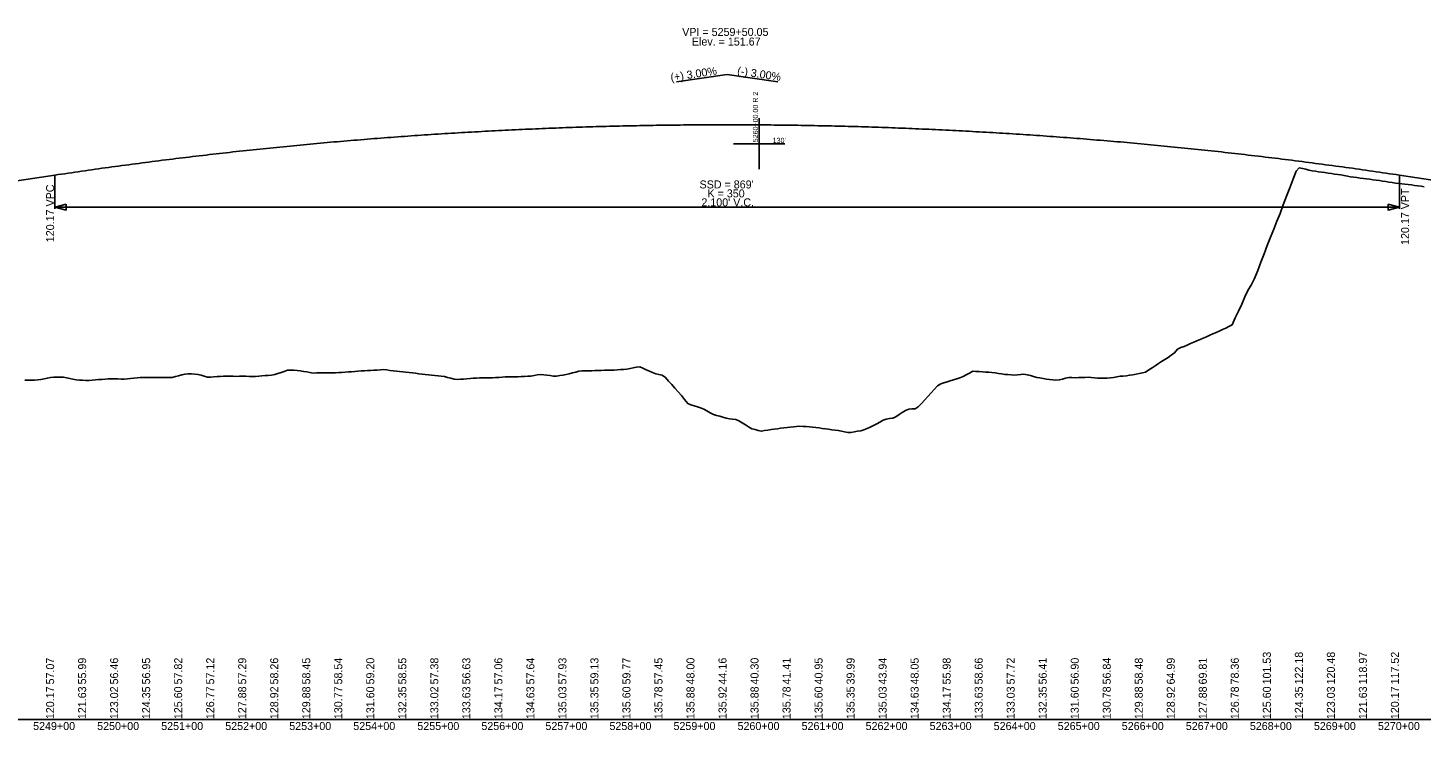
# Model space of a CAD drawing. Extents: x 2147288 to 2220488, y 740833 to 759333.
# Drawn here: x 2157239 to 2159415, y 742067 to 743164 of the extents above; entities that cross this region are included whole.
import ezdxf

# ---------------------------------------------------------------- set-up
doc = ezdxf.new("R2010")
doc.units = 0
for name, color, linetype in [('RD_DDB_GradeTX', 7, 'Continuous'), ('RD_DDB_Profile_EX', 7, 'Continuous'), ('RD_DDB_Profile_Lbl', 7, 'Continuous'), ('RD_DDB_Profile_PR', 7, 'Continuous'), ('RD_DDB_StaTX', 7, 'Continuous'), ('RD_DDB_StripGrade', 7, 'Continuous'), ('RD_DDB_VCLbl', 7, 'Continuous'), ('RD_GPK_Profile_Cell', 7, 'Continuous')]:
    doc.layers.add(name, color=color, linetype=linetype)

msp = doc.modelspace()

# ---------------------------------------------------------------- linework, layer by layer
at = {"layer": 'RD_DDB_GradeTX'}
for p in [(2158252, 743079.9), (2158410.2, 743079.9)]:
    msp.add_line(p, (2158331.1, 743091.8), dxfattribs=at)
at = {"layer": 'RD_DDB_Profile_EX'}
for points in [[(2159034.6, 742662.3), (2159039.6, 742664.7), (2159044.6, 742666.7), (2159049.6, 742668.8), (2159054.6, 742671), (2159059.6, 742673.2), (2159064.6, 742675.3), (2159069.6, 742677.5), (2159074.6, 742679.7), (2159079.6, 742681.8), (2159084.6, 742684), (2159089.6, 742686.2), (2159094.6, 742688.4), (2159099.6, 742690.5), (2159104.6, 742692.9), (2159109.6, 742695.3), (2159114.6, 742697.7), (2159119.6, 742700.4), (2159124.6, 742711.5), (2159129.6, 742721.9), (2159134.6, 742732.9), (2159139.6, 742744.3), (2159144.6, 742754.9), (2159149.6, 742762.3), (2159154.6, 742772.9), (2159159.6, 742785.4), (2159164.6, 742798.2), (2159169.6, 742811.2), (2159174.6, 742824.3), (2159179.6, 742837.3), (2159184.6, 742850), (2159189.6, 742862.4), (2159194.6, 742874.5), (2159199.6, 742887.8), (2159204.6, 742901.4), (2159209.6, 742914.5), (2159214.6, 742927.2), (2159219.6, 742940.4), (2159224.6, 742945.5), (2159229.6, 742944.7), (2159234.6, 742943.5), (2159239.6, 742942.3), (2159244.6, 742941.1), (2159249.6, 742940.4), (2159254.6, 742939.7), (2159259.6, 742939), (2159264.6, 742938.3), (2159269.6, 742937.5), (2159274.6, 742936.7), (2159279.6, 742936), (2159284.6, 742935.3), (2159289.6, 742934.6), (2159294.6, 742933.6), (2159299.6, 742932.7), (2159304.6, 742931.9), (2159309.6, 742931.2), (2159314.6, 742930.5), (2159319.6, 742929.8), (2159324.6, 742929.1), (2159329.6, 742928.5), (2159334.6, 742927.8), (2159339.6, 742927), (2159344.6, 742926.3), (2159349.6, 742925.7), (2159354.6, 742925), (2159359.6, 742924.2), (2159364.6, 742923.4), (2159369.6, 742922.7), (2159374.6, 742921.9), (2159379.6, 742921.2), (2159384.6, 742920.6), (2159389.6, 742920.2), (2159394.6, 742919.5), (2159399.6, 742918.9), (2159404.6, 742918.2), (2159409.6, 742917.6), (2159414.6, 742916.9), (2159419.6, 742916.2)], [(2158534.6, 742534), (2158539.6, 742534.8), (2158544.6, 742536.4), (2158549.6, 742538.4), (2158554.6, 742540.4), (2158559.6, 742542.9), (2158564.6, 742545.6), (2158569.6, 742548.4), (2158574.6, 742551.2), (2158579.6, 742552.8), (2158584.6, 742553.8), (2158589.6, 742554.7), (2158594.6, 742556.8), (2158599.6, 742560.1), (2158604.6, 742563.4), (2158609.6, 742566.7), (2158614.6, 742568.5), (2158619.6, 742568.9), (2158624.6, 742569.3), (2158629.6, 742572), (2158634.6, 742577.5), (2158639.6, 742583), (2158644.6, 742588.5), (2158649.6, 742594), (2158654.6, 742599.5), (2158659.6, 742605), (2158664.6, 742608.3), (2158669.6, 742609.8), (2158674.6, 742611.3), (2158679.6, 742612.8), (2158684.6, 742614.4), (2158689.6, 742616.1), (2158694.6, 742617.7), (2158699.6, 742619.4), (2158704.6, 742622.2), (2158709.6, 742625.1), (2158714.6, 742627.9), (2158719.6, 742627.5), (2158724.6, 742627.2), (2158729.6, 742626.8), (2158734.6, 742626.5), (2158739.6, 742626.2), (2158744.6, 742625.9), (2158749.6, 742625.3), (2158754.6, 742624.5), (2158759.6, 742623.7), (2158764.6, 742622.9), (2158769.6, 742622.6), (2158774.6, 742622.3), (2158779.6, 742621.9), (2158784.6, 742622.1), (2158789.6, 742622.6), (2158794.6, 742623.1), (2158799.6, 742622.4), (2158804.6, 742621), (2158809.6, 742619.6), (2158814.6, 742618.3), (2158819.6, 742617.4), (2158824.6, 742616.5), (2158829.6, 742615.7), (2158834.6, 742615), (2158839.6, 742614.4), (2158844.6, 742613.7), (2158849.6, 742614.3), (2158854.6, 742615.7), (2158859.6, 742617), (2158864.6, 742618), (2158869.6, 742617.9), (2158874.6, 742617.8), (2158879.6, 742617.9), (2158884.6, 742618), (2158889.6, 742618.2), (2158894.6, 742618.4), (2158899.6, 742618.1), (2158904.6, 742617.6), (2158909.6, 742617.1), (2158914.6, 742617), (2158919.6, 742617), (2158924.6, 742617), (2158929.6, 742617.4), (2158934.6, 742618.2), (2158939.6, 742619.1), (2158944.6, 742620), (2158949.6, 742620.4), (2158954.6, 742620.8), (2158959.6, 742621.5), (2158964.6, 742622.4), (2158969.6, 742623.3), (2158974.6, 742624.4), (2158979.6, 742625.5), (2158984.6, 742626.6), (2158989.6, 742629.9), (2158994.6, 742633.1), (2158999.6, 742636.4), (2159004.6, 742639.7), (2159009.6, 742642.9), (2159014.6, 742646.2), (2159019.6, 742649.4), (2159024.6, 742652.8), (2159029.6, 742656.7), (2159034.6, 742662.3)], [(2157534.6, 742619.4), (2157539.6, 742619.8), (2157544.6, 742619.9), (2157549.6, 742619.9), (2157554.6, 742620), (2157559.6, 742619.9), (2157564.6, 742619.8), (2157569.6, 742620), (2157574.6, 742620.1), (2157579.6, 742619.9), (2157584.6, 742619.7), (2157589.6, 742619.5), (2157594.6, 742619.7), (2157599.6, 742620.1), (2157604.6, 742620.6), (2157609.6, 742621), (2157614.6, 742621.3), (2157619.6, 742621.7), (2157624.6, 742622.5), (2157629.6, 742624.2), (2157634.6, 742626), (2157639.6, 742627.7), (2157644.6, 742629.5), (2157649.6, 742629.5), (2157654.6, 742629.4), (2157659.6, 742629.2), (2157664.6, 742628.5), (2157669.6, 742627.7), (2157674.6, 742626.8), (2157679.6, 742625.9), (2157684.6, 742625.1), (2157689.6, 742625.3), (2157694.6, 742625.4), (2157699.6, 742625.6), (2157704.6, 742625.6), (2157709.6, 742625.6), (2157714.6, 742625.6), (2157719.6, 742625.6), (2157724.6, 742625.7), (2157729.6, 742626), (2157734.6, 742626.3), (2157739.6, 742626.7), (2157744.6, 742627.1), (2157749.6, 742627.5), (2157754.6, 742628), (2157759.6, 742628.4), (2157764.6, 742628.7), (2157769.6, 742628.9), (2157774.6, 742629.1), (2157779.6, 742629.3), (2157784.6, 742629.7), (2157789.6, 742630.1), (2157794.6, 742630.4), (2157799.6, 742629.8), (2157804.6, 742629.2), (2157809.6, 742628.7), (2157814.6, 742628.1), (2157819.6, 742627.5), (2157824.6, 742626.9), (2157829.6, 742626.3), (2157834.6, 742625.8), (2157839.6, 742625.2), (2157844.6, 742624.6), (2157849.6, 742624), (2157854.6, 742623.4), (2157859.6, 742622.8), (2157864.6, 742622.3), (2157869.6, 742621.7), (2157874.6, 742621.1), (2157879.6, 742620.5), (2157884.6, 742619.9), (2157889.6, 742619.4), (2157894.6, 742618.3), (2157899.6, 742616.9), (2157904.6, 742615.5), (2157909.6, 742614.9), (2157914.6, 742615.3), (2157919.6, 742615.7), (2157924.6, 742616.1), (2157929.6, 742616.5), (2157934.6, 742616.8), (2157939.6, 742617.2), (2157944.6, 742617.6), (2157949.6, 742617.6), (2157954.6, 742617.6), (2157959.6, 742617.5), (2157964.6, 742617.7), (2157969.6, 742618), (2157974.6, 742618.3), (2157979.6, 742618.6), (2157984.6, 742618.9), (2157989.6, 742618.9), (2157994.6, 742619), (2157999.6, 742619), (2158004.6, 742619.3), (2158009.6, 742619.5), (2158014.6, 742619.8), (2158019.6, 742620), (2158024.6, 742620.4), (2158029.6, 742621.3), (2158034.6, 742622.2)], [(2158034.6, 742622.2), (2158039.6, 742622.8), (2158044.6, 742622.2), (2158049.6, 742621.6), (2158054.6, 742621), (2158059.6, 742620.4), (2158064.6, 742620.4), (2158069.6, 742621), (2158074.6, 742621.7), (2158079.6, 742622.7), (2158084.6, 742624), (2158089.6, 742625.3), (2158094.6, 742626.5), (2158099.6, 742627.8), (2158104.6, 742628.3), (2158109.6, 742628.4), (2158114.6, 742628.5), (2158119.6, 742628.6), (2158124.6, 742628.8), (2158129.6, 742629), (2158134.6, 742629.2), (2158139.6, 742629.4), (2158144.6, 742629.4), (2158149.6, 742629.4), (2158154.6, 742629.4), (2158159.6, 742629.9), (2158164.6, 742630.4), (2158169.6, 742630.8), (2158174.6, 742631.3), (2158179.6, 742631.9), (2158184.6, 742633.2), (2158189.6, 742634.4), (2158194.6, 742634.9), (2158199.6, 742632.6), (2158204.6, 742630.3), (2158209.6, 742628), (2158214.6, 742625.7), (2158219.6, 742624), (2158224.6, 742622.9), (2158229.6, 742621.8), (2158234.6, 742618.2), (2158239.6, 742612.6), (2158244.6, 742607), (2158249.6, 742601.4), (2158254.6, 742595.8), (2158259.6, 742589.8), (2158264.6, 742583.7), (2158269.6, 742577.5), (2158274.6, 742575.5), (2158279.6, 742573.9), (2158284.6, 742572.3), (2158289.6, 742570.7), (2158294.6, 742568.8), (2158299.6, 742565.9), (2158304.6, 742563), (2158309.6, 742560.4), (2158314.6, 742558.9), (2158319.6, 742557.4), (2158324.6, 742556), (2158329.6, 742554.5), (2158334.6, 742553.6), (2158339.6, 742553.2), (2158344.6, 742552.7), (2158349.6, 742550.6), (2158354.6, 742547.4), (2158359.6, 742544.1), (2158364.6, 742540.9), (2158369.6, 742537.9), (2158374.6, 742536.6), (2158379.6, 742535.3), (2158384.6, 742534.2), (2158389.6, 742535), (2158394.6, 742535.8), (2158399.6, 742536.6), (2158404.6, 742537.5), (2158409.6, 742538.1), (2158414.6, 742538.7), (2158419.6, 742539.2), (2158424.6, 742539.8), (2158429.6, 742540.3), (2158434.6, 742540.9), (2158439.6, 742541.4), (2158444.6, 742542), (2158449.6, 742541.7), (2158454.6, 742541.4), (2158459.6, 742541), (2158464.6, 742540.7), (2158469.6, 742540.1), (2158474.6, 742539.3), (2158479.6, 742538.4), (2158484.6, 742537.7), (2158489.6, 742537.1), (2158494.6, 742536.5), (2158499.6, 742535.9), (2158504.6, 742535.4), (2158509.6, 742534.3), (2158514.6, 742533.1), (2158519.6, 742531.9), (2158524.6, 742532.3), (2158529.6, 742533.1), (2158534.6, 742534)], [(2157234.6, 742614), (2157239.6, 742613.9), (2157244.6, 742613.9), (2157249.6, 742613.9), (2157254.6, 742614.2), (2157259.6, 742615.1), (2157264.6, 742616.1), (2157269.6, 742617.1), (2157274.6, 742618), (2157279.6, 742618.8), (2157284.6, 742618.7), (2157289.6, 742618.6), (2157294.6, 742618.4), (2157299.6, 742617.5), (2157304.6, 742616.5), (2157309.6, 742615.5), (2157314.6, 742614.5), (2157319.6, 742614), (2157324.6, 742613.7), (2157329.6, 742613.3), (2157334.6, 742613.4), (2157339.6, 742613.9), (2157344.6, 742614.3), (2157349.6, 742614.8), (2157354.6, 742615.2), (2157359.6, 742615.5), (2157364.6, 742615.8), (2157369.6, 742616.1), (2157374.6, 742615.9), (2157379.6, 742615.8), (2157384.6, 742615.6), (2157389.6, 742615.4), (2157394.6, 742615.9), (2157399.6, 742616.5), (2157404.6, 742617), (2157409.6, 742617.6), (2157414.6, 742617.9), (2157419.6, 742618), (2157424.6, 742618.1), (2157429.6, 742618.2), (2157434.6, 742618.1), (2157439.6, 742618.1), (2157444.6, 742618), (2157449.6, 742618), (2157454.6, 742618.1), (2157459.6, 742618.1), (2157464.6, 742618.2), (2157469.6, 742619.5), (2157474.6, 742620.8), (2157479.6, 742622.2), (2157484.6, 742623.5), (2157489.6, 742623.6), (2157494.6, 742623.6), (2157499.6, 742623.5), (2157504.6, 742622.8), (2157509.6, 742621.5), (2157514.6, 742620.1), (2157519.6, 742618.8), (2157524.6, 742618.4), (2157529.6, 742618.9), (2157534.6, 742619.4)]]:
    msp.add_lwpolyline(points, dxfattribs=at)
at = {"layer": 'RD_DDB_Profile_PR'}
for p, q in [((2156931.1, 742881.8), (2157281.1, 742934.3)), ((2159381.1, 742934.3), (2159706.2, 742885.5))]:
    msp.add_line(p, q, dxfattribs=at)
msp.add_spline([(2157281.1, 742934.3), (2157323.1, 742940.4), (2157365.1, 742946.4), (2157407.1, 742952), (2157449.1, 742957.5), (2157491.1, 742962.6), (2157533.1, 742967.5), (2157575.1, 742972.2), (2157617.1, 742976.6), (2157659.1, 742980.8), (2157701.1, 742984.7), (2157743.1, 742988.3), (2157785.1, 742991.7), (2157827.1, 742994.9), (2157869.1, 742997.8), (2157911.1, 743000.4), (2157953.1, 743002.8), (2157995.1, 743005), (2158037.1, 743006.8), (2158079.1, 743008.5), (2158121.1, 743009.9), (2158163.1, 743011), (2158205.1, 743011.9), (2158247.1, 743012.5), (2158289.1, 743012.9), (2158331.1, 743013), (2158373.1, 743012.9), (2158415.1, 743012.5), (2158457.1, 743011.9), (2158499.1, 743011), (2158541.1, 743009.9), (2158583.1, 743008.5), (2158625.1, 743006.8), (2158667.1, 743005), (2158709.1, 743002.8), (2158751.1, 743000.4), (2158793.1, 742997.8), (2158835.1, 742994.9), (2158877.1, 742991.7), (2158919.1, 742988.3), (2158961.1, 742984.7), (2159003.1, 742980.8), (2159045.1, 742976.6), (2159087.1, 742972.2), (2159129.1, 742967.5), (2159171.1, 742962.6), (2159213.1, 742957.5), (2159255.1, 742952), (2159297.1, 742946.4), (2159339.1, 742940.4), (2159381.1, 742934.3)], degree=3, dxfattribs=at)
at = {"layer": 'RD_DDB_VCLbl'}
for p, q in [((2157281.1, 742881.8), (2157281.1, 742934.3)), ((2159381.1, 742881.8), (2159381.1, 742934.3)), ((2157281.1, 742884.3), (2159381.1, 742884.3))]:
    msp.add_line(p, q, dxfattribs=at)
for points in [[(2157299.1, 742888.8), (2157281.1, 742884.3), (2157299.1, 742879.8)], [(2159363.1, 742888.8), (2159381.1, 742884.3), (2159363.1, 742879.8)]]:
    msp.add_lwpolyline(points, close=True, dxfattribs=at)
at = {"layer": 'RD_GPK_Profile_Cell'}
for p, q in [((2158381.1, 743023.4), (2158381.1, 742943.4)), ((2158421.1, 742983.4), (2158341.1, 742983.4)), ((2148888.3, 742083.4), (2165888.3, 742083.4))]:
    msp.add_line(p, q, dxfattribs=at)

# ---------------------------------------------------------------- texts
at = {"layer": 'RD_DDB_GradeTX'}
for s, rotation, p in [('(+) 3.00%', 8.5308, (2158243.6, 743080.7)), ('(-) 3.00%', 351.4692, (2158346.2, 743091.5))]:
    msp.add_text(s, height=12.5, rotation=rotation, dxfattribs=at).set_placement(p)
at = {"layer": 'RD_DDB_Profile_Lbl'}
for s, p in [('VPI = 5259+50.05', (2158260.9, 743151.8)), ('Elev. = 151.67', (2158276, 743136.8))]:
    msp.add_text(s, height=12.5, dxfattribs=at).set_placement(p)
at = {"layer": 'RD_DDB_StaTX'}
for s, p in [('5249+00', (2157247.3, 742067.2)), ('5250+00', (2157347.3, 742067.2)), ('5251+00', (2157447.3, 742067.2)), ('5252+00', (2157547.3, 742067.2)), ('5253+00', (2157647.3, 742067.2)), ('5254+00', (2157747.3, 742067.2)), ('5255+00', (2157847.3, 742067.2)), ('5256+00', (2157947.3, 742067.2)), ('5257+00', (2158047.3, 742067.2)), ('5258+00', (2158147.3, 742067.2)), ('5259+00', (2158247.3, 742067.2)), ('5260+00', (2158347.3, 742067.2)), ('5261+00', (2158447.3, 742067.2)), ('5262+00', (2158547.3, 742067.2)), ('5263+00', (2158647.3, 742067.2)), ('5264+00', (2158747.3, 742067.2)), ('5265+00', (2158847.3, 742067.2)), ('5266+00', (2158947.3, 742067.2)), ('5267+00', (2159047.3, 742067.2)), ('5268+00', (2159147.3, 742067.2)), ('5269+00', (2159247.3, 742067.2)), ('5270+00', (2159347.3, 742067.2))]:
    msp.add_text(s, height=12.5, dxfattribs=at).set_placement(p)
at = {"layer": 'RD_DDB_StripGrade'}
for s, p in [('120.17 VPC', (2157280.1, 742829.5)), ('120.17 VPT', (2159396, 742825.2)), ('101.53', (2159180.1, 742138.4)), ('122.18', (2159230.1, 742138.4)), ('120.48', (2159280.1, 742138.4)), ('118.97', (2159330.1, 742138.4)), ('117.52', (2159380.1, 742138.4)), ('57.07', (2157280.1, 742138.4)), ('55.99', (2157330.1, 742138.4)), ('56.46', (2157380.1, 742138.4)), ('56.95', (2157430.1, 742138.4)), ('57.82', (2157480.1, 742138.4)), ('57.12', (2157530.1, 742138.4)), ('57.29', (2157580.1, 742138.4)), ('58.26', (2157630.1, 742138.4)), ('58.45', (2157680.1, 742138.4)), ('58.54', (2157730.1, 742138.4)), ('59.20', (2157780.1, 742138.4)), ('58.55', (2157830.1, 742138.4)), ('57.38', (2157880.1, 742138.4)), ('56.63', (2157930.1, 742138.4)), ('57.06', (2157980.1, 742138.4)), ('57.64', (2158030.1, 742138.4)), ('57.93', (2158080.1, 742138.4)), ('59.13', (2158130.1, 742138.4)), ('59.77', (2158180.1, 742138.4)), ('57.45', (2158230.1, 742138.4)), ('48.00', (2158280.1, 742138.4)), ('44.16', (2158330.1, 742138.4)), ('40.30', (2158380.1, 742138.4)), ('41.41', (2158430.1, 742138.4)), ('40.95', (2158480.1, 742138.4)), ('39.99', (2158530.1, 742138.4)), ('43.94', (2158580.1, 742138.4)), ('48.05', (2158630.1, 742138.4)), ('55.98', (2158680.1, 742138.4)), ('58.66', (2158730.1, 742138.4)), ('57.72', (2158780.1, 742138.4)), ('56.41', (2158830.1, 742138.4)), ('56.90', (2158880.1, 742138.4)), ('56.84', (2158930.1, 742138.4)), ('58.48', (2158980.1, 742138.4)), ('64.99', (2159030.1, 742138.4)), ('69.81', (2159080.1, 742138.4)), ('78.36', (2159130.1, 742138.4)), ('120.17', (2157280.1, 742084.2)), ('121.63', (2157330.1, 742084.2)), ('123.02', (2157380.1, 742084.2)), ('124.35', (2157430.1, 742084.2)), ('125.60', (2157480.1, 742084.2)), ('126.77', (2157530.1, 742084.2)), ('127.88', (2157580.1, 742084.2)), ('128.92', (2157630.1, 742084.2)), ('129.88', (2157680.1, 742084.2)), ('130.77', (2157730.1, 742084.2)), ('131.60', (2157780.1, 742084.2)), ('132.35', (2157830.1, 742084.2)), ('133.02', (2157880.1, 742084.2)), ('133.63', (2157930.1, 742084.2)), ('134.17', (2157980.1, 742084.2)), ('134.63', (2158030.1, 742084.2)), ('135.03', (2158080.1, 742084.2)), ('135.35', (2158130.1, 742084.2)), ('135.60', (2158180.1, 742084.2)), ('135.78', (2158230.1, 742084.2)), ('135.88', (2158280.1, 742084.2)), ('135.92', (2158330.1, 742084.2)), ('135.88', (2158380.1, 742084.2)), ('135.78', (2158430.1, 742084.2)), ('135.60', (2158480.1, 742084.2)), ('135.35', (2158530.1, 742084.2)), ('135.03', (2158580.1, 742084.2)), ('134.63', (2158630.1, 742084.2)), ('134.17', (2158680.1, 742084.2)), ('133.63', (2158730.1, 742084.2)), ('133.03', (2158780.1, 742084.2)), ('132.35', (2158830.1, 742084.2)), ('131.60', (2158880.1, 742084.2)), ('130.78', (2158930.1, 742084.2)), ('129.88', (2158980.1, 742084.2)), ('128.92', (2159030.1, 742084.2)), ('127.88', (2159080.1, 742084.2)), ('126.78', (2159130.1, 742084.2)), ('125.60', (2159180.1, 742084.2)), ('124.35', (2159230.1, 742084.2)), ('123.03', (2159280.1, 742084.2)), ('121.63', (2159330.1, 742084.2)), ('120.17', (2159380.1, 742084.2))]:
    msp.add_text(s, height=12.5, rotation=90, dxfattribs=at).set_placement(p)
at = {"layer": 'RD_DDB_VCLbl'}
for s, p in [("SSD = 869'", (2158288, 742913.5)), ('K = 350', (2158300.4, 742899.5)), ("2,100' V.C.", (2158290.9, 742885.5))]:
    msp.add_text(s, height=12.5, dxfattribs=at).set_placement(p)
at = {"layer": 'RD_GPK_Profile_Cell'}
msp.add_text('5260+00.00 R 2', height=8, rotation=90, dxfattribs=at).set_placement((2158379.3, 742985.7))
msp.add_text("130'", height=8, dxfattribs=at).set_placement((2158402.2, 742984.6))

doc.saveas('drawing.dxf')
